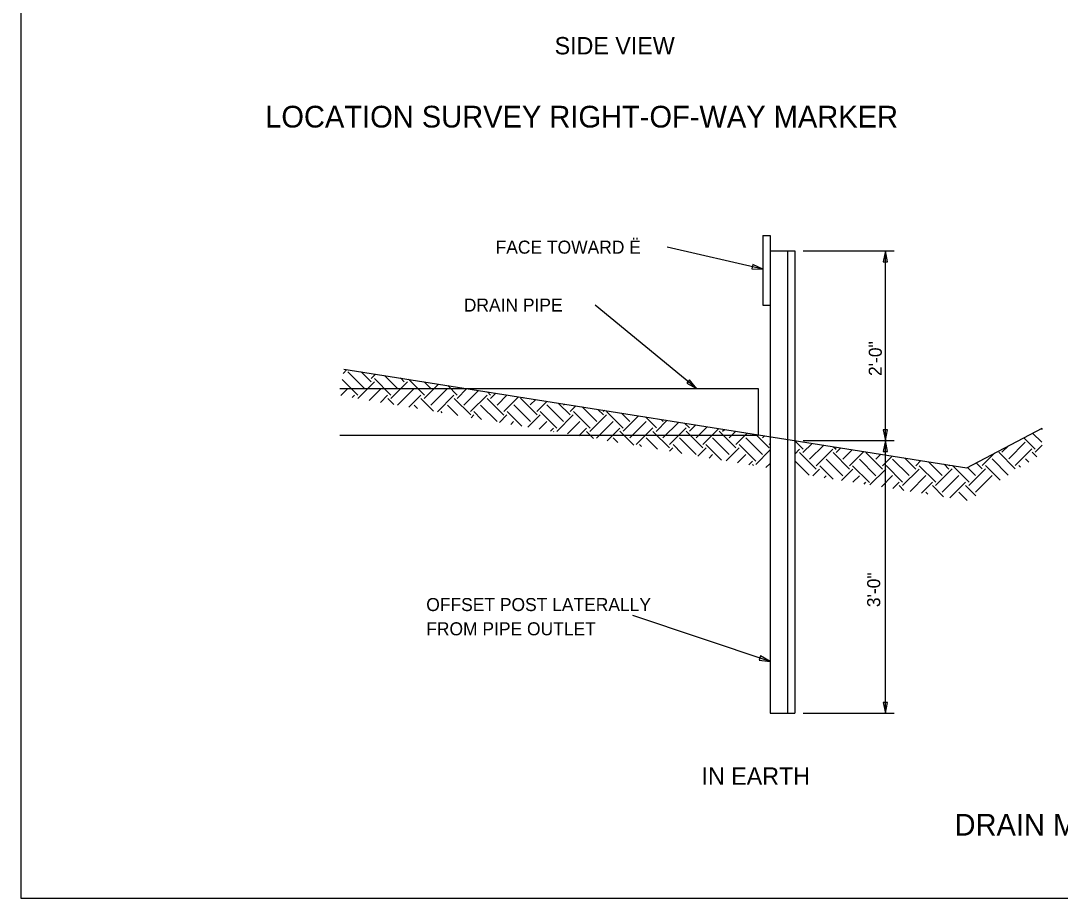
# Model space of a CAD drawing. Extents: x -439.1 to -407.9, y -458.1 to -436.2.
# Drawn here: x -439.11 to -427.15, y -458.05 to -447.96 of the extents above; entities that cross this region are included whole.
import ezdxf

# ---------------------------------------------------------------- set-up
doc = ezdxf.new("R2010")
doc.units = 0
for name, color, linetype in [('Bridge-Named Boundary', 7, 'Continuous'), ('Level 4', 7, 'Continuous'), ('Level 45', 7, 'Continuous')]:
    doc.layers.add(name, color=color, linetype=linetype)

msp = doc.modelspace()

# ---------------------------------------------------------------- linework, layer by layer
at = {"layer": 'Bridge-Named Boundary'}
msp.add_lwpolyline([(-439.109, -458.051), (-407.859, -458.051), (-407.859, -437.676), (-439.109, -437.676)], close=True, dxfattribs=at)
at = {"layer": 'Level 4'}
for p, q in [((-430.571, -450.427), (-430.571, -451.23)), ((-430.571, -450.427), (-430.488, -450.427)), ((-430.488, -450.427), (-430.488, -455.922)), ((-430.571, -450.816), (-431.671, -450.561)), ((-430.488, -450.604), (-430.205, -450.604)), ((-430.288, -450.604), (-430.288, -455.922)), ((-430.205, -450.604), (-430.205, -455.922)), ((-430.107, -450.605), (-429.061, -450.605)), ((-429.162, -452.786), (-429.162, -450.605)), ((-431.336, -452.187), (-432.501, -451.228)), ((-430.571, -451.23), (-430.488, -451.23)), ((-435.4, -452.015), (-435.356, -451.97)), ((-435.393, -451.964), (-428.225, -453.1)), ((-435.345, -451.997), (-435.153, -452.189)), ((-435.193, -451.996), (-435.077, -452.112)), ((-435.079, -452.074), (-435.027, -452.022)), ((-434.924, -452.039), (-434.774, -452.189)), ((-435.411, -452.084), (-435.23, -452.265)), ((-435.232, -452.303), (-435.041, -452.112)), ((-435.041, -452.074), (-434.85, -452.265)), ((-434.851, -452.302), (-434.66, -452.111)), ((-434.742, -452.067), (-434.697, -452.112)), ((-434.648, -452.082), (-434.466, -452.264)), ((-434.469, -452.302), (-434.303, -452.137)), ((-434.467, -452.111), (-434.39, -452.188)), ((-434.197, -452.154), (-434.087, -452.264)), ((-435.439, -452.187), (-430.626, -452.187)), ((-435.428, -452.269), (-435.347, -452.189)), ((-435.297, -452.292), (-435.27, -452.265)), ((-435.101, -452.325), (-434.964, -452.189)), ((-434.97, -452.347), (-434.888, -452.265)), ((-434.775, -452.379), (-434.584, -452.188)), ((-434.645, -452.402), (-434.507, -452.264)), ((-434.392, -452.379), (-434.201, -452.188)), ((-434.316, -452.455), (-434.125, -452.264)), ((-434.088, -452.301), (-433.976, -452.189)), ((-434.015, -452.183), (-434.01, -452.188)), ((-434.011, -452.378), (-433.843, -452.21)), ((-433.935, -452.454), (-433.744, -452.263)), ((-433.74, -452.226), (-433.703, -452.263)), ((-433.706, -452.301), (-433.645, -452.241)), ((-433.629, -452.378), (-433.513, -452.262)), ((-433.553, -452.454), (-433.382, -452.283)), ((-430.626, -452.187), (-430.626, -452.725)), ((-434.887, -452.302), (-434.816, -452.373)), ((-434.584, -452.379), (-434.543, -452.419)), ((-434.507, -452.302), (-434.359, -452.45)), ((-434.2, -452.378), (-434.08, -452.498)), ((-434.124, -452.301), (-433.932, -452.492)), ((-433.82, -452.378), (-433.629, -452.569)), ((-433.744, -452.301), (-433.553, -452.493)), ((-433.437, -452.377), (-433.246, -452.568)), ((-433.36, -452.3), (-433.169, -452.491)), ((-433.324, -452.3), (-433.318, -452.293)), ((-433.248, -452.377), (-433.185, -452.314)), ((-433.171, -452.453), (-433.053, -452.335)), ((-433.057, -452.377), (-432.866, -452.568)), ((-432.926, -452.355), (-432.789, -452.492)), ((-432.866, -452.377), (-432.855, -452.367)), ((-432.789, -452.453), (-432.724, -452.387)), ((-432.65, -452.399), (-432.482, -452.567)), ((-434.276, -452.454), (-434.264, -452.467)), ((-433.928, -452.524), (-433.896, -452.492)), ((-433.897, -452.454), (-433.807, -452.544)), ((-433.603, -452.579), (-433.516, -452.491)), ((-433.513, -452.453), (-433.343, -452.623)), ((-433.276, -452.634), (-433.133, -452.491)), ((-433.133, -452.453), (-432.942, -452.644)), ((-432.943, -452.681), (-432.752, -452.49)), ((-432.75, -452.452), (-432.558, -452.643)), ((-432.561, -452.682), (-432.37, -452.49)), ((-432.468, -452.428), (-432.406, -452.49)), ((-432.408, -452.452), (-432.395, -452.439)), ((-432.37, -452.452), (-432.179, -452.643)), ((-432.199, -452.471), (-432.102, -452.567)), ((-432.18, -452.68), (-432.001, -452.502)), ((-431.923, -452.514), (-431.795, -452.642)), ((-433.472, -452.601), (-433.439, -452.568)), ((-433.145, -452.656), (-433.057, -452.568)), ((-433.015, -452.678), (-432.98, -452.644)), ((-432.82, -452.711), (-432.676, -452.567)), ((-432.689, -452.733), (-432.599, -452.643)), ((-432.484, -452.758), (-432.293, -452.567)), ((-432.363, -452.789), (-432.217, -452.643)), ((-432.103, -452.757), (-431.912, -452.566)), ((-432.027, -452.833), (-431.836, -452.642)), ((-431.798, -452.681), (-431.671, -452.554)), ((-431.742, -452.543), (-431.719, -452.566)), ((-431.721, -452.757), (-431.539, -452.575)), ((-431.645, -452.833), (-431.454, -452.642)), ((-431.472, -452.586), (-431.416, -452.642)), ((-431.417, -452.679), (-431.343, -452.606)), ((-431.34, -452.756), (-431.211, -452.627)), ((-428.225, -453.1), (-427.358, -452.644)), ((-435.439, -452.725), (-430.626, -452.725)), ((-432.979, -452.681), (-432.975, -452.685)), ((-432.6, -452.682), (-432.519, -452.762)), ((-432.292, -452.757), (-432.239, -452.81)), ((-432.216, -452.68), (-432.055, -452.841)), ((-431.912, -452.757), (-431.782, -452.887)), ((-431.836, -452.681), (-431.645, -452.872)), ((-431.529, -452.756), (-431.338, -452.947)), ((-431.452, -452.679), (-431.261, -452.871)), ((-431.263, -452.832), (-431.079, -452.648)), ((-431.149, -452.756), (-430.958, -452.947)), ((-431.073, -452.68), (-430.882, -452.871)), ((-431.034, -452.68), (-431.013, -452.659)), ((-430.958, -452.756), (-430.881, -452.679)), ((-430.882, -452.832), (-430.75, -452.7)), ((-430.766, -452.755), (-430.574, -452.946)), ((-430.651, -452.716), (-430.498, -452.87)), ((-430.577, -452.755), (-430.553, -452.731)), ((-427.567, -452.754), (-427.438, -452.884)), ((-427.467, -452.701), (-427.361, -452.807)), ((-427.367, -452.649), (-427.358, -452.658)), ((-431.989, -452.833), (-431.966, -452.856)), ((-431.647, -452.91), (-431.608, -452.871)), ((-431.605, -452.832), (-431.503, -452.934)), ((-431.32, -452.965), (-431.225, -452.871)), ((-431.226, -452.832), (-431.046, -453.012)), ((-430.995, -453.02), (-430.844, -452.87)), ((-430.842, -452.831), (-430.651, -453.022)), ((-430.5, -452.831), (-430.488, -452.819)), ((-430.205, -452.788), (-430.107, -452.886)), ((-430.11, -452.925), (-430.004, -452.819)), ((-430.107, -452.786), (-429.061, -452.786)), ((-430.107, -452.786), (-429.165, -452.786)), ((-430.033, -453.001), (-429.871, -452.84)), ((-429.757, -452.858), (-429.728, -452.887)), ((-429.729, -452.923), (-429.676, -452.871)), ((-429.162, -455.922), (-429.162, -452.786)), ((-427.82, -452.922), (-427.746, -452.848)), ((-427.743, -452.998), (-427.552, -452.807)), ((-427.667, -453.075), (-427.476, -452.883)), ((-427.439, -452.92), (-427.359, -452.841)), ((-431.189, -452.988), (-431.149, -452.947)), ((-430.864, -453.043), (-430.768, -452.946)), ((-430.653, -453.061), (-430.488, -452.895)), ((-430.205, -452.944), (-430.148, -452.887)), ((-430.148, -452.925), (-429.957, -453.116)), ((-429.957, -453.078), (-429.766, -452.886)), ((-429.841, -453), (-429.65, -453.191)), ((-429.764, -452.923), (-429.573, -453.115)), ((-429.652, -453), (-429.544, -452.892)), ((-429.576, -453.077), (-429.411, -452.912)), ((-429.461, -453), (-429.27, -453.191)), ((-429.385, -452.924), (-429.194, -453.115)), ((-429.346, -452.924), (-429.346, -452.923)), ((-429.27, -453), (-429.213, -452.944)), ((-429.194, -453.077), (-429.082, -452.965)), ((-429.078, -452.999), (-428.886, -453.19)), ((-428.936, -452.988), (-428.81, -453.114)), ((-428.889, -452.999), (-428.886, -452.996)), ((-428.049, -453.075), (-427.907, -452.933)), ((-427.934, -452.998), (-427.748, -453.184)), ((-427.858, -452.922), (-427.667, -453.113)), ((-427.551, -452.997), (-427.513, -453.035)), ((-427.474, -452.92), (-427.42, -452.975)), ((-430.733, -453.065), (-430.691, -453.023)), ((-430.692, -453.061), (-430.678, -453.074)), ((-430.537, -453.098), (-430.488, -453.049)), ((-430.205, -453.02), (-430.04, -453.186)), ((-429.998, -453.193), (-429.92, -453.115)), ((-429.917, -453.076), (-429.764, -453.23)), ((-429.668, -453.245), (-429.537, -453.115)), ((-429.538, -453.077), (-429.346, -453.268)), ((-429.34, -453.297), (-429.157, -453.114)), ((-429.154, -453.075), (-428.963, -453.266)), ((-428.965, -453.305), (-428.774, -453.114)), ((-428.812, -453.076), (-428.753, -453.017)), ((-428.774, -453.076), (-428.583, -453.267)), ((-428.666, -453.031), (-428.507, -453.19)), ((-428.584, -453.304), (-428.393, -453.113)), ((-428.485, -453.059), (-428.43, -453.114)), ((-428.43, -453.076), (-428.424, -453.069)), ((-428.39, -453.074), (-428.199, -453.265)), ((-428.217, -453.096), (-428.123, -453.189)), ((-428.202, -453.304), (-428.011, -453.113)), ((-428.116, -453.043), (-428.047, -453.113)), ((-428.011, -453.075), (-427.842, -453.244)), ((-427.627, -453.073), (-427.606, -453.094)), ((-429.866, -453.214), (-429.843, -453.191)), ((-429.536, -453.266), (-429.461, -453.191)), ((-429.208, -453.318), (-429.08, -453.19)), ((-428.878, -453.371), (-428.697, -453.19)), ((-428.508, -453.38), (-428.317, -453.189)), ((-428.125, -453.38), (-427.934, -453.189)), ((-429.404, -453.287), (-429.385, -453.267)), ((-429.076, -453.34), (-429.003, -453.267)), ((-429.004, -453.305), (-428.949, -453.36)), ((-428.747, -453.392), (-428.621, -453.266)), ((-428.62, -453.304), (-428.491, -453.433)), ((-428.419, -453.444), (-428.24, -453.266)), ((-428.24, -453.304), (-428.122, -453.423)), ((-428.696, -453.38), (-428.673, -453.404)), ((-428.317, -453.38), (-428.221, -453.476)), ((-430.488, -455.328), (-432.067, -454.798)), ((-430.488, -455.922), (-430.205, -455.922)), ((-430.107, -455.922), (-429.061, -455.922))]:
    msp.add_line(p, q, dxfattribs=at)
for points in [[(-429.136, -450.729), (-429.162, -450.605), (-429.188, -450.729)], [(-430.698, -450.813), (-430.571, -450.816), (-430.686, -450.763)], [(-430.698, -450.813), (-430.571, -450.816), (-430.686, -450.763)], [(-431.447, -452.126), (-431.336, -452.187), (-431.414, -452.087)], [(-429.188, -452.662), (-429.162, -452.786), (-429.136, -452.662)], [(-429.136, -452.911), (-429.162, -452.786), (-429.188, -452.911)], [(-430.614, -455.313), (-430.488, -455.328), (-430.598, -455.264)], [(-430.614, -455.313), (-430.488, -455.328), (-430.598, -455.264)], [(-429.188, -455.798), (-429.162, -455.922), (-429.136, -455.798)]]:
    msp.add_lwpolyline(points, close=True, dxfattribs=at)

# ---------------------------------------------------------------- texts
for s, height, p in [('SIDE VIEW', 0.2, (-432.967, -448.345)), ('LOCATION SURVEY RIGHT-OF-WAY MARKER', 0.25, (-436.297, -449.186)), ('FACE TOWARD Ë', 0.15, (-433.646, -450.637)), ('DRAIN PIPE', 0.15, (-434.012, -451.303)), ('OFFSET POST LATERALLY', 0.15, (-434.444, -454.748)), ('FROM PIPE OUTLET', 0.15, (-434.444, -455.027)), ('IN EARTH', 0.2, (-431.277, -456.746)), ('DRAIN MARKER', 0.25, (-428.366, -457.331))]:
    msp.add_text(s, height=height, dxfattribs=at).set_placement(p)
at = {"layer": 'Level 45'}
for s, p in [('2\'-0"', (-429.203, -452.044)), ('3\'-0"', (-429.221, -454.703))]:
    msp.add_text(s, height=0.15, rotation=90, dxfattribs=at).set_placement(p)

doc.saveas('drawing.dxf')
